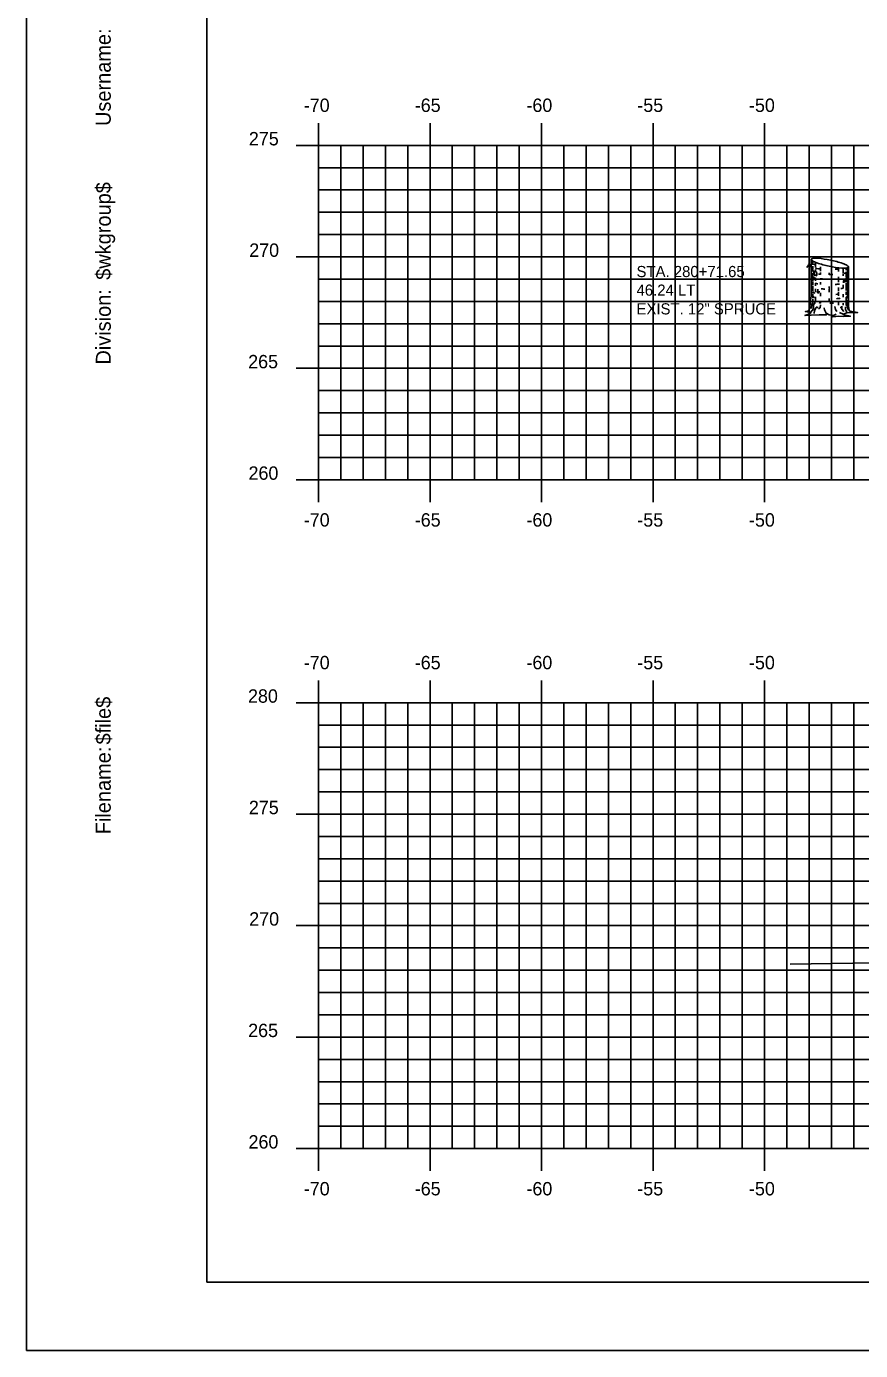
# Model space of a CAD drawing. Extents: x 855344 to 855514, y 366268 to 366378.
# Drawn here: x 855344 to 855381.4, y 366268.2 to 366327.6 of the extents above; entities that cross this region are included whole.
import ezdxf

# ---------------------------------------------------------------- set-up
doc = ezdxf.new("R2010")
doc.units = 0
for name, color, linetype in [('BORDER', 7, 'Continuous'), ('D_Text_Monospaced', 7, 'Continuous'), ('H_V ANNOTATION', 7, 'Continuous'), ('MAJOR', 7, 'Continuous'), ('MINOR', 7, 'Continuous'), ('PLOT BOUNDARY', 7, 'Continuous'), ('S_Roadway_Centerline', 7, 'Continuous'), ('S_Trees_Conifer_Pay', 7, 'Continuous')]:
    doc.layers.add(name, color=color, linetype=linetype)

msp = doc.modelspace()

# ---------------------------------------------------------------- linework, layer by layer
at = {"layer": 'BORDER'}
for p, q in [((855352.11, 366376.236), (855352.11, 366271.236)), ((855352.11, 366271.236), (855512.11, 366271.236))]:
    msp.add_line(p, q, dxfattribs=at)
at = {"layer": 'MAJOR'}
for p, q in [((855357.11, 366323.238), (855357.11, 366322.236)), ((855362.11, 366323.238), (855362.11, 366322.236)), ((855367.11, 366323.238), (855367.11, 366322.236)), ((855372.11, 366323.238), (855372.11, 366322.236)), ((855377.11, 366323.238), (855377.11, 366322.236)), ((855356.108, 366322.236), (855357.11, 366322.236)), ((855357.11, 366322.236), (855497.11, 366322.236)), ((855357.11, 366307.236), (855357.11, 366322.236)), ((855357.11, 366307.236), (855357.11, 366322.236)), ((855357.11, 366322.236), (855497.11, 366322.236)), ((855362.11, 366307.236), (855362.11, 366322.236)), ((855367.11, 366307.236), (855367.11, 366322.236)), ((855372.11, 366307.236), (855372.11, 366322.236)), ((855377.11, 366307.236), (855377.11, 366322.236)), ((855356.108, 366317.236), (855357.11, 366317.236)), ((855357.11, 366317.236), (855497.11, 366317.236)), ((855356.108, 366312.236), (855357.11, 366312.236)), ((855357.11, 366312.236), (855497.11, 366312.236)), ((855356.108, 366307.236), (855357.11, 366307.236)), ((855357.11, 366307.236), (855497.11, 366307.236)), ((855357.11, 366307.236), (855497.11, 366307.236)), ((855357.11, 366306.234), (855357.11, 366307.236)), ((855362.11, 366306.234), (855362.11, 366307.236)), ((855367.11, 366306.234), (855367.11, 366307.236)), ((855372.11, 366306.234), (855372.11, 366307.236)), ((855377.11, 366306.234), (855377.11, 366307.236)), ((855357.11, 366298.238), (855357.11, 366297.236)), ((855362.11, 366298.238), (855362.11, 366297.236)), ((855367.11, 366298.238), (855367.11, 366297.236)), ((855372.11, 366298.238), (855372.11, 366297.236)), ((855377.11, 366298.238), (855377.11, 366297.236)), ((855356.108, 366297.236), (855357.11, 366297.236)), ((855357.11, 366297.236), (855497.11, 366297.236)), ((855357.11, 366277.236), (855357.11, 366297.236)), ((855357.11, 366277.236), (855357.11, 366297.236)), ((855357.11, 366297.236), (855497.11, 366297.236)), ((855362.11, 366277.236), (855362.11, 366297.236)), ((855367.11, 366277.236), (855367.11, 366297.236)), ((855372.11, 366277.236), (855372.11, 366297.236)), ((855377.11, 366277.236), (855377.11, 366297.236)), ((855356.108, 366292.236), (855357.11, 366292.236)), ((855357.11, 366292.236), (855497.11, 366292.236)), ((855356.108, 366287.236), (855357.11, 366287.236)), ((855357.11, 366287.236), (855497.11, 366287.236)), ((855356.108, 366282.236), (855357.11, 366282.236)), ((855357.11, 366282.236), (855497.11, 366282.236)), ((855356.108, 366277.236), (855357.11, 366277.236)), ((855357.11, 366277.236), (855497.11, 366277.236)), ((855357.11, 366277.236), (855497.11, 366277.236)), ((855357.11, 366276.234), (855357.11, 366277.236)), ((855362.11, 366276.234), (855362.11, 366277.236)), ((855367.11, 366276.234), (855367.11, 366277.236)), ((855372.11, 366276.234), (855372.11, 366277.236)), ((855377.11, 366276.234), (855377.11, 366277.236))]:
    msp.add_line(p, q, dxfattribs=at)
at = {"layer": 'MINOR'}
for p, q in [((855357.11, 366307.236), (855357.11, 366322.236)), ((855358.11, 366307.236), (855358.11, 366322.236)), ((855359.11, 366307.236), (855359.11, 366322.236)), ((855360.11, 366307.236), (855360.11, 366322.236)), ((855361.11, 366307.236), (855361.11, 366322.236)), ((855363.11, 366307.236), (855363.11, 366322.236)), ((855364.11, 366307.236), (855364.11, 366322.236)), ((855365.11, 366307.236), (855365.11, 366322.236)), ((855366.11, 366307.236), (855366.11, 366322.236)), ((855368.11, 366307.236), (855368.11, 366322.236)), ((855369.11, 366307.236), (855369.11, 366322.236)), ((855370.11, 366307.236), (855370.11, 366322.236)), ((855371.11, 366307.236), (855371.11, 366322.236)), ((855373.11, 366307.236), (855373.11, 366322.236)), ((855374.11, 366307.236), (855374.11, 366322.236)), ((855375.11, 366307.236), (855375.11, 366322.236)), ((855376.11, 366307.236), (855376.11, 366322.236)), ((855378.11, 366307.236), (855378.11, 366322.236)), ((855379.11, 366307.236), (855379.11, 366322.236)), ((855380.11, 366307.236), (855380.11, 366322.236)), ((855381.11, 366307.236), (855381.11, 366322.236)), ((855357.11, 366321.236), (855497.11, 366321.236)), ((855357.11, 366321.236), (855358.112, 366321.236)), ((855357.11, 366320.236), (855497.11, 366320.236)), ((855357.11, 366320.236), (855358.112, 366320.236)), ((855357.11, 366319.236), (855497.11, 366319.236)), ((855357.11, 366319.236), (855358.112, 366319.236)), ((855357.11, 366318.236), (855497.11, 366318.236)), ((855357.11, 366318.236), (855358.112, 366318.236)), ((855357.11, 366316.236), (855497.11, 366316.236)), ((855357.11, 366316.236), (855358.112, 366316.236)), ((855357.11, 366315.236), (855497.11, 366315.236)), ((855357.11, 366315.236), (855358.112, 366315.236)), ((855357.11, 366314.236), (855497.11, 366314.236)), ((855357.11, 366314.236), (855358.112, 366314.236)), ((855357.11, 366313.236), (855497.11, 366313.236)), ((855357.11, 366313.236), (855358.112, 366313.236)), ((855357.11, 366311.236), (855497.11, 366311.236)), ((855357.11, 366311.236), (855358.112, 366311.236)), ((855357.11, 366310.236), (855497.11, 366310.236)), ((855357.11, 366310.236), (855358.112, 366310.236)), ((855357.11, 366309.236), (855497.11, 366309.236)), ((855357.11, 366309.236), (855358.112, 366309.236)), ((855357.11, 366308.236), (855497.11, 366308.236)), ((855357.11, 366308.236), (855358.112, 366308.236)), ((855357.11, 366277.236), (855357.11, 366297.236)), ((855358.11, 366277.236), (855358.11, 366297.236)), ((855359.11, 366277.236), (855359.11, 366297.236)), ((855360.11, 366277.236), (855360.11, 366297.236)), ((855361.11, 366277.236), (855361.11, 366297.236)), ((855363.11, 366277.236), (855363.11, 366297.236)), ((855364.11, 366277.236), (855364.11, 366297.236)), ((855365.11, 366277.236), (855365.11, 366297.236)), ((855366.11, 366277.236), (855366.11, 366297.236)), ((855368.11, 366277.236), (855368.11, 366297.236)), ((855369.11, 366277.236), (855369.11, 366297.236)), ((855370.11, 366277.236), (855370.11, 366297.236)), ((855371.11, 366277.236), (855371.11, 366297.236)), ((855373.11, 366277.236), (855373.11, 366297.236)), ((855374.11, 366277.236), (855374.11, 366297.236)), ((855375.11, 366277.236), (855375.11, 366297.236)), ((855376.11, 366277.236), (855376.11, 366297.236)), ((855378.11, 366277.236), (855378.11, 366297.236)), ((855379.11, 366277.236), (855379.11, 366297.236)), ((855380.11, 366277.236), (855380.11, 366297.236)), ((855381.11, 366277.236), (855381.11, 366297.236)), ((855357.11, 366296.236), (855497.11, 366296.236)), ((855357.11, 366296.236), (855358.112, 366296.236)), ((855357.11, 366295.236), (855497.11, 366295.236)), ((855357.11, 366295.236), (855358.112, 366295.236)), ((855357.11, 366294.236), (855497.11, 366294.236)), ((855357.11, 366294.236), (855358.112, 366294.236)), ((855357.11, 366293.236), (855497.11, 366293.236)), ((855357.11, 366293.236), (855358.112, 366293.236)), ((855357.11, 366291.236), (855497.11, 366291.236)), ((855357.11, 366291.236), (855358.112, 366291.236)), ((855357.11, 366290.236), (855497.11, 366290.236)), ((855357.11, 366290.236), (855358.112, 366290.236)), ((855357.11, 366289.236), (855497.11, 366289.236)), ((855357.11, 366289.236), (855358.112, 366289.236)), ((855357.11, 366288.236), (855497.11, 366288.236)), ((855357.11, 366288.236), (855358.112, 366288.236)), ((855357.11, 366286.236), (855497.11, 366286.236)), ((855357.11, 366286.236), (855358.112, 366286.236)), ((855357.11, 366285.236), (855497.11, 366285.236)), ((855357.11, 366285.236), (855358.112, 366285.236)), ((855357.11, 366284.236), (855497.11, 366284.236)), ((855357.11, 366284.236), (855358.112, 366284.236)), ((855357.11, 366283.236), (855497.11, 366283.236)), ((855357.11, 366283.236), (855358.112, 366283.236)), ((855357.11, 366281.236), (855497.11, 366281.236)), ((855357.11, 366281.236), (855358.112, 366281.236)), ((855357.11, 366280.236), (855497.11, 366280.236)), ((855357.11, 366280.236), (855358.112, 366280.236)), ((855357.11, 366279.236), (855497.11, 366279.236)), ((855357.11, 366279.236), (855358.112, 366279.236)), ((855357.11, 366278.236), (855497.11, 366278.236)), ((855357.11, 366278.236), (855358.112, 366278.236))]:
    msp.add_line(p, q, dxfattribs=at)
at = {"layer": 'PLOT BOUNDARY'}
msp.add_lwpolyline([(855344.016, 366268.177), (855514.016, 366268.177), (855514.016, 366378.177), (855344.016, 366378.177)], close=True, dxfattribs=at)
at = {"layer": 'S_Roadway_Centerline'}
msp.add_lwpolyline([(855378.254, 366285.511), (855393.27, 366285.747), (855406.881, 366285.969), (855407.512, 366285.951), (855408.987, 366285.898), (855411.293, 366285.775), (855413.068, 366285.862), (855416.618, 366286.097), (855424.003, 366286.406), (855427.383, 366286.558), (855434.651, 366286.447), (855438.341, 366286.386), (855441.994, 366286.262), (855443.249, 366286.287), (855444.06, 366286.162), (855446.795, 366286.149), (855448.857, 366286.219), (855460.22, 366286.692)], dxfattribs=at)
at = {"layer": 'S_Trees_Conifer_Pay'}
for p, q in [((855379.207, 366315.473), (855379.207, 366317.12)), ((855379.279, 366317.048), (855379.279, 366316.885)), ((855379.279, 366316.818), (855379.279, 366316.69)), ((855379.279, 366316.503), (855379.279, 366316.167)), ((855379.396, 366316.987), (855379.396, 366316.764)), ((855379.396, 366316.675), (855379.396, 366316.628)), ((855379.625, 366316.791), (855379.625, 366316.591)), ((855379.625, 366316.533), (855379.625, 366316.445)), ((855380.015, 366316.517), (855380.015, 366316.422)), ((855380.421, 366316.749), (855380.421, 366316.581)), ((855380.64, 366316.728), (855380.64, 366316.496)), ((855380.766, 366316.736), (855380.766, 366316.638)), ((855380.766, 366316.564), (855380.766, 366316.36)), ((855380.824, 366316.747), (855380.824, 366316.276)), ((855380.871, 366315.063), (855380.871, 366316.785)), ((855379.279, 366316.13), (855379.279, 366315.967)), ((855379.279, 366315.92), (855379.279, 366315.703)), ((855379.339, 366316.492), (855379.39, 366316.432)), ((855379.396, 366316.293), (855379.396, 366316.161)), ((855379.396, 366316.05), (855379.396, 366315.94)), ((855379.625, 366316.097), (855379.625, 366315.992)), ((855380.421, 366316.344), (855380.421, 366316.107)), ((855380.64, 366316.455), (855380.64, 366316.381)), ((855380.64, 366315.978), (855380.64, 366315.839)), ((855380.766, 366316.302), (855380.766, 366316.103)), ((855380.766, 366316.056), (855380.766, 366315.72)), ((855380.824, 366316.212), (855380.824, 366315.904)), ((855379.279, 366315.673), (855379.279, 366315.598)), ((855379.279, 366315.558), (855379.279, 366315.384)), ((855379.396, 366315.804), (855379.396, 366315.663)), ((855379.396, 366315.436), (855379.396, 366315.263)), ((855379.625, 366315.625), (855379.625, 366315.479)), ((855380.015, 366315.904), (855380.015, 366315.829)), ((855380.015, 366315.804), (855380.015, 366315.656)), ((855380.015, 366315.364), (855380.015, 366315.211)), ((855380.421, 366315.862), (855380.421, 366315.71)), ((855380.421, 366315.667), (855380.421, 366315.493)), ((855380.64, 366315.568), (855380.64, 366315.426)), ((855380.766, 366315.667), (855380.766, 366315.531)), ((855380.766, 366315.432), (855380.766, 366315.053)), ((855380.824, 366315.856), (855380.824, 366315.364)), ((855379.625, 366315.247), (855379.625, 366315.158)), ((855380.421, 366315.216), (855380.421, 366315.063)), ((855380.64, 366314.67), (855380.478, 366314.734)), ((855380.64, 366315.164), (855380.64, 366315.07)), ((855380.824, 366315.31), (855380.824, 366315.063)), ((855380.203, 366314.606), (855380.329, 366314.67))]:
    msp.add_line(p, q, dxfattribs=at)
for points in [[(855379.161, 366316.851), (855379.086, 366316.859), (855379.014, 366316.76)], [(855379.39, 366316.618), (855379.354, 366316.544), (855379.306, 366316.601), (855379.249, 366316.669), (855379.156, 366316.863), (855379.092, 366316.91), (855379.061, 366316.917)], [(855379.376, 366316.365), (855379.339, 366316.492), (855379.276, 366316.608), (855379.245, 366316.675), (855379.176, 366316.821)], [(855379.424, 366316.581), (855379.455, 366316.496), (855379.459, 366316.428), (855379.428, 366316.365)], [(855380.692, 366316.091), (855380.698, 366316.186), (855380.655, 366316.163), (855380.655, 366316.068)], [(855379.207, 366315.473), (855379.156, 366315.211), (855379.14, 366314.938), (855379.082, 366314.812), (855378.946, 366314.781), (855379.176, 366314.744), (855379.176, 366314.744), (855379.171, 366314.697), (855378.923, 366314.602), (855379.197, 366314.619), (855379.553, 366314.639), (855379.875, 366314.629), (855379.868, 366314.711), (855380.016, 366314.629), (855380.203, 366314.606), (855380.179, 366314.538), (855380.447, 366314.581), (855380.667, 366314.554), (855380.96, 366314.571), (855380.671, 366314.629), (855380.64, 366314.67), (855380.803, 366314.728), (855381.04, 366314.738), (855381.281, 366314.738), (855380.939, 366314.796), (855380.898, 366314.876), (855380.871, 366315.063)], [(855379.281, 366315.331), (855379.276, 366315.185), (855379.228, 366315.117), (855379.218, 366314.917)], [(855379.553, 366315.692), (855379.541, 366315.615), (855379.493, 366315.625), (855379.506, 366315.792)], [(855379.381, 366315.185), (855379.306, 366315.08), (855379.302, 366314.907), (855379.176, 366314.744)], [(855379.339, 366314.691), (855379.354, 366314.829), (855379.428, 366314.958)], [(855379.617, 366315.08), (855379.607, 366314.954), (855379.533, 366314.911)], [(855379.868, 366314.711), (855379.794, 366314.853), (855379.784, 366314.954)], [(855380.356, 366314.781), (855380.289, 366314.876), (855380.262, 366315.016)], [(855380.583, 366315.022), (855380.583, 366314.89), (855380.671, 366314.791)], [(855380.745, 366314.995), (855380.739, 366314.88), (855380.793, 366314.791), (855380.803, 366314.728)], [(855380.823, 366315.016), (855380.844, 366314.938), (855380.865, 366314.843)]]:
    msp.add_lwpolyline(points, dxfattribs=at)
for centre, radius, start, end in [((855379.23, 366317.12), 0.0226, 168.2806, 179.96855), ((855379.234, 366317.12), 0.0264, 179.96855, 190.7806), ((855379.23, 366317.12), 0.0226, 156.59265, 168.2806), ((855379.239, 366317.121), 0.0314, 190.7806, 203.48418), ((855379.233, 366317.119), 0.0264, 145.7806, 156.59265), ((855379.258, 366317.13), 0.0527, 203.48418, 213.2806), ((855379.237, 366317.116), 0.0314, 133.07702, 145.7806), ((855379.282, 366317.146), 0.0817, 213.2806, 227.61132), ((855379.252, 366317.1), 0.0527, 123.2806, 133.07702), ((855379.268, 366317.076), 0.0817, 108.94987, 123.2806), ((855379.323, 366316.916), 0.251, 100.7806, 108.94987), ((855379.426, 366316.375), 0.802, 84.62059, 100.7806), ((855379.015, 366312.017), 5.179, 78.2806, 84.62059), ((855379.24, 366316.994), 0.0334, 185.78494, 196.05154), ((855379.24, 366316.839), 0.0334, 185.78494, 196.05154), ((855379.251, 366316.997), 0.0441, 196.05154, 210), ((855379.251, 366316.842), 0.0441, 196.05154, 210), ((855379.267, 366317.006), 0.0624, 210, 228.74941), ((855379.267, 366316.851), 0.0624, 210, 228.74941), ((855379.339, 366317.089), 0.172, 228.74941, 240), ((855379.339, 366316.934), 0.172, 228.74941, 240), ((855379.396, 366317.27), 0.251, 227.61132, 235.7806), ((855379.538, 366317.279), 0.571, 240, 242.9763), ((855379.706, 366317.726), 0.802, 235.7806, 251.94061), ((855379.538, 366317.434), 0.571, 247.58675, 255.56834), ((855379.538, 366317.279), 0.571, 255.63335, 261.8968), ((855381.063, 366321.887), 5.179, 251.94061, 258.2806), ((855380.039, 366320.797), 4.124, 261.8968, 263.76196), ((855381.063, 366321.887), 5.179, 258.2806, 264.62059), ((855379.015, 366312.017), 5.179, 71.94061, 78.2806), ((855380.039, 366320.797), 4.124, 273.26691, 275.3045), ((855380.653, 366317.53), 0.802, 264.62059, 280.7806), ((855380.372, 366316.179), 0.802, 55.7806, 71.94061), ((855380.541, 366317.046), 0.571, 282.01543, 293.14027), ((855380.756, 366316.988), 0.251, 280.7806, 288.94988), ((855380.682, 366316.634), 0.251, 47.61132, 55.7806), ((855380.541, 366317.046), 0.571, 299.66328, 300), ((855380.741, 366316.701), 0.172, 300, 311.25059), ((855380.811, 366316.829), 0.0817, 288.94988, 303.2806), ((855380.796, 366316.759), 0.0817, 33.2806, 47.61132), ((855380.813, 366316.619), 0.0624, 311.25059, 330), ((855380.826, 366316.804), 0.0527, 303.2806, 313.07702), ((855380.841, 366316.789), 0.0314, 313.07702, 325.7806), ((855380.82, 366316.775), 0.0527, 23.48418, 33.2806), ((855380.845, 366316.786), 0.0264, 325.7806, 336.59265), ((855380.829, 366316.609), 0.0441, 330, 343.94846), ((855380.84, 366316.784), 0.0314, 10.7806, 23.48418), ((855380.849, 366316.784), 0.0226, 336.59265, 348.2806), ((855380.845, 366316.784), 0.0264, 359.96855, 10.7806), ((855380.849, 366316.784), 0.0226, 348.2806, 359.96855), ((855380.839, 366316.606), 0.0334, 0, 16.05154), ((855380.839, 366316.606), 0.0334, 343.94846, 360), ((855379.241, 366316.395), 0.0334, 185.78494, 196.05154), ((855379.242, 366316.16), 0.0334, 185.78494, 196.05154), ((855379.242, 366315.95), 0.0334, 185.78494, 196.05154), ((855379.252, 366316.163), 0.0441, 196.05154, 210), ((855379.252, 366315.953), 0.0441, 196.05154, 210), ((855379.268, 366316.172), 0.0624, 210, 228.74941), ((855379.268, 366315.962), 0.0624, 210, 228.74941), ((855379.341, 366316.254), 0.172, 228.74941, 240), ((855379.341, 366316.044), 0.172, 228.74941, 240), ((855379.54, 366316.599), 0.571, 240, 242.81041), ((855379.538, 366316.835), 0.571, 242.95715, 255.55072), ((855379.54, 366316.599), 0.571, 253.07038, 261.8968), ((855380.041, 366320.117), 4.124, 261.8968, 262.38753), ((855380.041, 366320.564), 4.124, 262.94416, 264.21507), ((855380.039, 366320.353), 4.124, 264.04957, 266.29476), ((855380.041, 366320.564), 4.124, 269.64186, 270), ((855380.041, 366320.564), 4.124, 270, 271.92488), ((855380.041, 366320.117), 4.124, 273.33241, 275.91902), ((855380.54, 366316.835), 0.571, 292.94134, 300), ((855380.541, 366316.599), 0.571, 299.66328, 300), ((855380.741, 366316.254), 0.172, 300, 311.25059), ((855380.741, 366316.044), 0.172, 300, 311.25059), ((855380.813, 366316.172), 0.0624, 311.25059, 330), ((855380.813, 366315.962), 0.0624, 311.25059, 330), ((855380.829, 366316.163), 0.0441, 330, 343.94846), ((855380.829, 366315.953), 0.0441, 330, 343.94846), ((855380.839, 366316.16), 0.0334, 0, 16.05154), ((855380.839, 366316.16), 0.0334, 343.94846, 360), ((855380.839, 366315.95), 0.0334, 0, 16.05154), ((855380.839, 366315.95), 0.0334, 343.94846, 360), ((855379.242, 366315.515), 0.0334, 185.78494, 196.05154), ((855379.252, 366315.518), 0.0441, 196.05154, 210), ((855379.268, 366315.527), 0.0624, 210, 228.74941), ((855379.341, 366315.61), 0.172, 228.74941, 240), ((855379.54, 366316.389), 0.571, 240, 242.81041), ((855379.54, 366315.955), 0.571, 240, 250.70928), ((855379.54, 366316.153), 0.571, 242.81041, 254.60173), ((855380.041, 366319.907), 4.124, 264.54309, 266.85066), ((855380.041, 366319.907), 4.124, 269.64186, 270), ((855380.041, 366319.67), 4.124, 273.68066, 275.28397), ((855380.041, 366319.473), 4.124, 274.16025, 276.50094), ((855380.041, 366319.907), 4.124, 276.85262, 278.1032), ((855380.541, 366316.389), 0.571, 278.1032, 280.72928), ((855380.541, 366316.389), 0.571, 293.14027, 300), ((855380.541, 366316.153), 0.571, 293.14027, 300), ((855380.552, 366315.961), 0.571, 291.97323, 298.76314), ((855380.741, 366315.808), 0.172, 300, 311.25059), ((855380.813, 366315.725), 0.0624, 311.25059, 330), ((855380.829, 366315.716), 0.0441, 330, 343.94846), ((855380.839, 366315.713), 0.0334, 0, 16.05154), ((855380.839, 366315.713), 0.0334, 343.94846, 360), ((855380.839, 366315.515), 0.0334, 0, 16.05154), ((855380.839, 366315.32), 0.0334, 0, 16.05154), ((855380.839, 366315.32), 0.0334, 343.94846, 360), ((855379.242, 366315.099), 0.0334, 185.78494, 196.05154), ((855379.252, 366315.102), 0.0441, 196.05154, 210), ((855379.268, 366315.111), 0.0624, 210, 228.74941), ((855379.341, 366315.194), 0.172, 228.74941, 240), ((855379.54, 366315.759), 0.571, 242.72792, 251.49327), ((855379.54, 366315.539), 0.571, 258.36297, 261.8968), ((855380.041, 366319.057), 4.124, 261.8968, 262.63158), ((855380.041, 366319.277), 4.124, 263.21039, 264.21507), ((855380.041, 366319.277), 4.124, 269.86721, 270), ((855380.041, 366319.277), 4.124, 270, 272.18834), ((855380.041, 366319.057), 4.124, 276.48798, 277.55621), ((855380.541, 366315.759), 0.571, 293.14027, 300), ((855380.541, 366315.539), 0.571, 295.46862, 300), ((855380.741, 366315.414), 0.172, 300, 311.25059), ((855380.741, 366315.194), 0.172, 300, 311.25059), ((855380.813, 366315.332), 0.0624, 311.25059, 330), ((855380.813, 366315.111), 0.0624, 311.25059, 330), ((855380.829, 366315.323), 0.0441, 330, 343.94846), ((855380.829, 366315.102), 0.0441, 330, 343.94846), ((855380.839, 366315.099), 0.0334, 0, 16.05154), ((855380.839, 366315.099), 0.0334, 343.94846, 360)]:
    msp.add_arc(centre, radius, start, end, dxfattribs=at)

# ---------------------------------------------------------------- texts
at = {"layer": 'BORDER'}
for s, p in [('Username:', (855347.795, 366323.104)), ('$wkgroup$', (855347.795, 366316.206)), ('Division:', (855347.795, 366312.403)), ('$file$', (855347.795, 366295.362)), ('Filename:', (855347.795, 366291.335))]:
    msp.add_text(s, height=0.6696, rotation=90, dxfattribs=at).set_placement(p)
at = {"layer": 'D_Text_Monospaced'}
for s, height, p in [('STA. 280+71.65', 0.49998, (855371.37, 366316.328)), ('46.24 LT.', 0.5, (855371.37, 366315.494)), ('EXIST. 12" SPRUCE', 0.49998, (855371.37, 366314.654))]:
    msp.add_text(s, height=height, dxfattribs=at).set_placement(p)
at = {"layer": 'H_V ANNOTATION'}
for s, p in [('-70', (855356.451, 366323.736)), ('-65', (855361.427, 366323.736)), ('-60', (855366.435, 366323.736)), ('-55', (855371.406, 366323.736)), ('-50', (855376.414, 366323.736)), ('275', (855353.988, 366322.236)), ('270', (855354.004, 366317.236)), ('265', (855353.956, 366312.236)), ('260', (855353.972, 366307.236)), ('-70', (855356.451, 366305.136)), ('-65', (855361.427, 366305.136)), ('-60', (855366.435, 366305.136)), ('-55', (855371.406, 366305.136)), ('-50', (855376.414, 366305.136)), ('-70', (855356.451, 366298.736)), ('-65', (855361.427, 366298.736)), ('-60', (855366.435, 366298.736)), ('-55', (855371.406, 366298.736)), ('-50', (855376.414, 366298.736)), ('280', (855353.95, 366297.236)), ('275', (855353.988, 366292.236)), ('270', (855354.004, 366287.236)), ('265', (855353.956, 366282.236)), ('260', (855353.972, 366277.236)), ('-70', (855356.451, 366275.136)), ('-65', (855361.427, 366275.136)), ('-60', (855366.435, 366275.136)), ('-55', (855371.406, 366275.136)), ('-50', (855376.414, 366275.136))]:
    msp.add_text(s, height=0.6, dxfattribs=at).set_placement(p)

doc.saveas('drawing.dxf')
